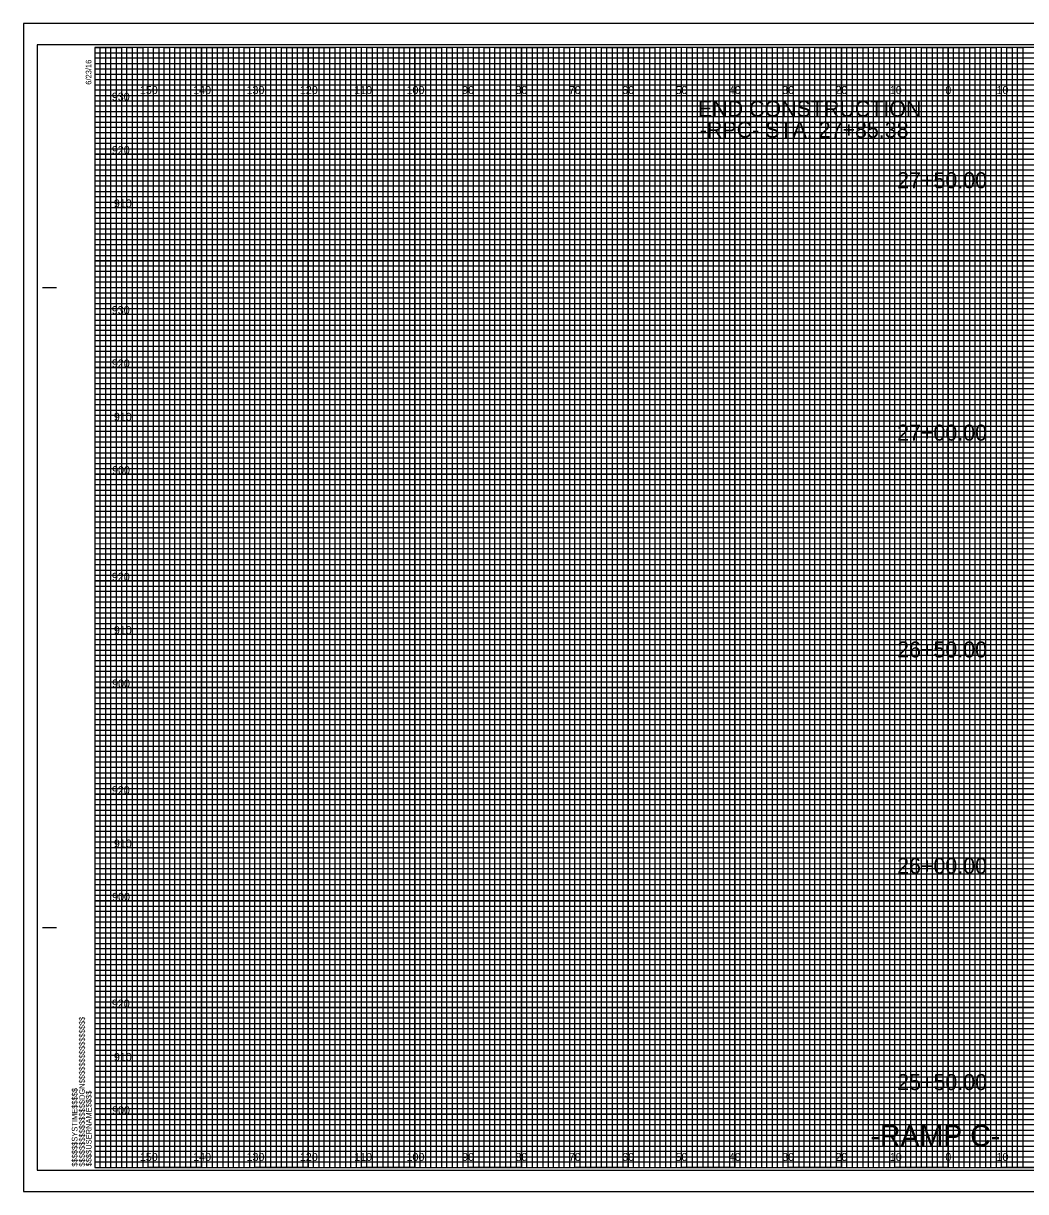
# Model space of a CAD drawing. Extents: x -13 to 323, y 876 to 1094.
# Drawn here: x -13.4 to 174.5, y 875.5 to 1094.5 of the extents above; entities that cross this region are included whole.
import ezdxf

# ---------------------------------------------------------------- set-up
doc = ezdxf.new("R2010")
doc.units = 0
for name, color, linetype in [('Prop XS Alignment Label', 7, 'Continuous'), ('Prop XS Elevation Labels', 7, 'Continuous'), ('Prop XS Offset Labels', 7, 'Continuous'), ('Prop XS SE Text', 7, 'Continuous'), ('Prop XS Station Labels', 7, 'Continuous'), ('Sheet Cross Section CELL', 7, 'Continuous'), ('Sheet Cross Section Grid Major CELL', 7, 'Continuous'), ('Sheet Cross Section Grid Middle CELL', 7, 'Continuous'), ('Sheet Cross Section Grid Minor 1 CELL', 7, 'Continuous'), ('Sheet Cross Section Grid Minor 2 CELL', 7, 'Continuous'), ('Sheet Cutting Line CELL', 7, 'Continuous'), ('Sheet DOT Grid CELL', 7, 'Continuous'), ('Sheet Plot Border Inside CELL', 7, 'Continuous'), ('Sheet Plot Border Outside CELL', 7, 'Continuous')]:
    doc.layers.add(name, color=color, linetype=linetype)

msp = doc.modelspace()

# ---------------------------------------------------------------- linework, layer by layer
at = {"layer": 'Sheet Cross Section CELL'}
for p, q in [((-9.8, 1045), (-7.3, 1045)), ((-9.7, 1045), (-7.2, 1045)), ((-9.8, 925), (-7.3, 925)), ((-9.7, 925), (-7.2, 925)), ((0, 880), (0, 880)), ((0, 880), (0, 880)), ((0, 880), (0, 880)), ((0, 880), (0, 880)), ((0, 880), (0, 880)), ((0, 880), (0, 880)), ((0, 880), (0, 880))]:
    msp.add_line(p, q, dxfattribs=at)
msp.add_lwpolyline([(320, 1090), (0, 1090), (0, 880), (320, 880)], close=True, dxfattribs=at)
at = {"layer": 'Sheet Cross Section Grid Major CELL'}
for p, q in [((10, 1090), (0, 1090)), ((10, 880), (10, 1090)), ((30, 1090), (20, 1090)), ((20, 1090), (20, 880)), ((30, 880), (30, 1090)), ((50, 1090), (40, 1090)), ((40, 1090), (40, 880)), ((50, 880), (50, 1090)), ((70, 1090), (60, 1090)), ((60, 1090), (60, 880)), ((70, 880), (70, 1090)), ((90, 1090), (80, 1090)), ((80, 1090), (80, 880)), ((90, 880), (90, 1090)), ((110, 1090), (100, 1090)), ((100, 1090), (100, 880)), ((110, 880), (110, 1090)), ((130, 1090), (120, 1090)), ((120, 1090), (120, 880)), ((130, 880), (130, 1090)), ((150, 1090), (140, 1090)), ((140, 1090), (140, 880)), ((150, 880), (150, 1090)), ((170, 1090), (160, 1090)), ((160, 1090), (160, 880)), ((170, 880), (170, 1090)), ((20, 880), (10, 880)), ((40, 880), (30, 880)), ((60, 880), (50, 880)), ((80, 880), (70, 880)), ((100, 880), (90, 880)), ((120, 880), (110, 880)), ((140, 880), (130, 880)), ((160, 880), (150, 880)), ((180, 880), (170, 880))]:
    msp.add_line(p, q, dxfattribs=at)
for points in [[(0, 1080), (320, 1080), (320, 1070), (0, 1070)], [(0, 1060), (320, 1060), (320, 1050), (0, 1050)], [(0, 1040), (320, 1040), (320, 1030), (0, 1030)], [(0, 1020), (320, 1020), (320, 1010), (0, 1010)], [(0, 1000), (320, 1000), (320, 990), (0, 990)], [(0, 980), (320, 980), (320, 970), (0, 970)], [(0, 960), (320, 960), (320, 950), (0, 950)], [(0, 940), (320, 940), (320, 930), (0, 930)], [(0, 920), (320, 920), (320, 910), (0, 910)], [(0, 900), (320, 900), (320, 890), (0, 890)]]:
    msp.add_lwpolyline(points, dxfattribs=at)
at = {"layer": 'Sheet Cross Section Grid Middle CELL'}
for points in [[(0, 1090), (5, 1090), (5, 880), (15, 880), (15, 1090), (25, 1090), (25, 880), (35, 880), (35, 1090), (45, 1090), (45, 880), (55, 880), (55, 1090), (65, 1090), (65, 880), (75, 880), (75, 1090), (85, 1090), (85, 880), (95, 880), (95, 1090), (105, 1090), (105, 880), (115, 880), (115, 1090), (125, 1090), (125, 880), (135, 880), (135, 1090), (145, 1090), (145, 880), (155, 880), (155, 1090), (165, 1090), (165, 880), (175, 880)], [(0, 1085), (275, 1085)], [(0, 1065), (320, 1065), (320, 1075), (0, 1075)], [(0, 1045), (320, 1045), (320, 1055), (0, 1055)], [(0, 1025), (320, 1025), (320, 1035), (0, 1035)], [(0, 1005), (320, 1005), (320, 1015), (0, 1015)], [(0, 985), (320, 985), (320, 995), (0, 995)], [(0, 965), (320, 965), (320, 975), (0, 975)], [(0, 945), (320, 945), (320, 955), (0, 955)], [(0, 925), (320, 925), (320, 935), (0, 935)], [(0, 905), (320, 905), (320, 915), (0, 915)], [(0, 885), (320, 885), (320, 895), (0, 895)]]:
    msp.add_lwpolyline(points, dxfattribs=at)
at = {"layer": 'Sheet Cross Section Grid Minor 1 CELL'}
for p, q in [((0, 1089), (260, 1089)), ((260, 1087.98), (0, 1087.98)), ((0, 1087.98), (0, 1087)), ((0, 1087), (260, 1087)), ((260, 1085.89), (0, 1085.89)), ((0, 1085.89), (0, 1084)), ((0, 1084), (320, 1084))]:
    msp.add_line(p, q, dxfattribs=at)
for points in [[(0, 1083), (270, 1083), (320, 1083), (320, 1082), (0, 1082)], [(0, 1081), (320, 1081), (320, 1079), (0, 1079)], [(0, 1078), (320, 1078), (320, 1077), (0, 1076.98)], [(0, 1076), (320, 1076), (320, 1074), (0, 1074)], [(0, 1073), (320, 1073), (320, 1072), (0, 1072)], [(0, 1071), (320, 1071), (320, 1069), (0, 1069)], [(0, 1068), (320, 1068), (320, 1067), (0, 1067)], [(0, 1066), (320, 1066), (320, 1064), (0, 1064)], [(0, 1063), (320, 1063), (320, 1062), (0, 1062)], [(0, 1061), (320, 1061), (320, 1059), (0, 1059)], [(0, 1058), (320, 1058), (320, 1057), (0, 1057)], [(0, 1056), (320, 1056), (320, 1053.95), (320, 1053), (320, 1052), (0, 1052)], [(0, 1054), (320, 1054), (320, 1053), (0, 1053)], [(0, 1051), (320, 1051), (320, 1049), (0, 1049.03)], [(0, 1049.03), (320, 1049), (320, 1048), (0, 1048)], [(0, 1047), (320, 1047), (320, 1046), (0, 1046)], [(0, 1044), (320, 1044), (320, 1043), (0, 1043)], [(0, 1042), (320, 1042), (320, 1041), (0, 1041)], [(-0.07, 1038.89), (320, 1038.89), (320, 1037.88), (-0.07, 1037.88)], [(0, 1037), (320, 1037), (320, 1036), (0, 1036)], [(0, 1034), (320, 1034), (320, 1033), (0, 1033)], [(0, 1032), (320, 1032), (320, 1031), (0, 1031)], [(0, 1029), (320, 1029), (320, 1028), (0, 1028)], [(0, 1027), (320, 1027), (320, 1026), (0, 1026)], [(0, 1024), (320, 1024), (320, 1023), (0, 1023)], [(0, 1022), (320, 1022), (320, 1021), (0, 1021)], [(0, 1019), (320, 1019), (319.99, 1017.98), (0, 1018)], [(0, 1017), (320, 1017), (320, 1016), (0, 1016)], [(0, 1014), (320, 1014), (320, 1013), (0, 1013)], [(0, 1012), (320, 1012), (320, 1011), (0, 1011)], [(0, 1009), (320, 1009), (320, 1008), (0, 1008)], [(0, 1007), (320, 1007), (320, 1006), (0, 1006)], [(0, 1004), (320, 1004), (320, 1003), (0, 1003)], [(0, 1002), (320, 1002), (320, 1001), (0, 1001)], [(0, 999), (320, 999), (320, 998), (0, 998)], [(0, 996.99), (320.07, 996.91), (320, 996), (0, 996)], [(0, 994), (320, 994), (320, 993), (0, 993)], [(0, 992), (320, 992), (320, 991), (0, 991)], [(0, 989), (320, 989), (320, 988), (0, 988)], [(0, 987), (320, 987), (320, 986), (0, 986)], [(0, 984), (320, 984), (320, 983), (0, 983)], [(0, 982), (320, 982), (320, 981), (0, 981)], [(0, 979), (320, 979), (320, 978), (0, 978)], [(0, 977), (320, 977), (320, 976), (0, 976)], [(0, 974), (320, 974), (320, 973), (0, 973)], [(0, 972), (320, 972), (320, 971), (0, 971)], [(0, 969), (320, 969), (320, 968), (0, 968)], [(0, 967), (320, 967), (320, 966), (0, 966)], [(0, 964), (320, 964), (320, 963), (0, 963)], [(0, 962), (320, 962), (320, 961), (0, 961)], [(0, 959), (320, 959), (319.99, 957.98), (0, 958)], [(0, 957), (320, 957), (320, 956), (0, 956)], [(0, 954), (320, 954), (320, 953), (0, 953)], [(0, 952), (320, 952), (320, 951), (0, 951)], [(0, 949), (320, 949), (320, 948), (0, 948)], [(0, 947), (320, 947), (320, 946), (0, 946)], [(0, 944), (320, 944), (320, 943), (0, 943)], [(0, 942), (320, 942), (320, 941), (0, 941)], [(0, 939), (320, 939), (320, 938), (0, 938)], [(0, 936.99), (320.07, 936.91), (320, 936), (0, 936)], [(0, 934), (320, 934), (320, 933), (0, 933)], [(0, 932), (320, 932), (320, 931), (0, 931)], [(0, 929), (320, 929), (320, 928), (0, 928)], [(0, 927), (320, 927), (320, 926), (0, 926)], [(0, 924), (320, 924), (320, 923), (0, 923)], [(0, 922), (320, 922), (320, 921), (0, 921)], [(0, 919), (320, 919), (320, 918), (0, 918)], [(0, 917), (320, 917), (320, 916), (0, 916)], [(0, 914), (320, 914), (320, 913), (0, 913)], [(0, 912), (320, 912), (320, 911), (0, 911)], [(0, 909), (320, 909), (320, 908), (0, 908)], [(0, 907), (320, 907), (320, 906), (0, 906)], [(0, 904), (320, 904), (320, 903), (0, 903)], [(0, 902), (320, 902), (320, 901), (0, 901)], [(0, 899), (320, 899), (320, 898), (0, 898)], [(0, 897), (320, 897), (320, 896), (0, 896)], [(0, 894), (320, 894), (320, 893), (0, 893)], [(0, 892), (320, 892), (320, 891), (0, 891)], [(0, 889), (320, 889), (320, 888), (0, 888)], [(0, 887), (320, 887), (320, 886), (0, 886)], [(0, 884), (320, 884), (320, 883), (0, 883)], [(0, 882), (320, 882), (320, 881), (0, 881)]]:
    msp.add_lwpolyline(points, dxfattribs=at)
at = {"layer": 'Sheet Cross Section Grid Minor 2 CELL'}
for points in [[(0, 880), (1, 880), (1, 1090), (2, 1090), (2, 880)], [(2, 880), (3, 880), (3, 1090), (4, 1090), (4, 880)], [(5, 880), (6, 880), (6, 1090), (7, 1090), (7, 880)], [(7, 880), (8, 880), (8, 1090), (9, 1090), (9, 880)], [(10, 880), (11, 880), (11, 1090), (12, 1090), (12, 880)], [(12, 880), (13, 880), (13, 1090), (14, 1090), (14, 880)], [(15, 880), (16, 880), (16, 1090), (17, 1090), (17, 880)], [(17, 880), (18, 880), (18, 1090), (19, 1090), (19, 880)], [(20, 880), (21, 880), (21, 1090), (22, 1090), (22, 880)], [(22, 880), (23, 880), (23, 1090), (24, 1090), (24, 880)], [(25, 880), (26, 880), (26, 1090), (27, 1090), (27, 880)], [(27, 880), (28, 880), (28, 1090), (29, 1090), (29, 880)], [(30, 880), (31, 880), (31, 1090), (32, 1090), (32, 880)], [(32, 880), (33, 880), (33, 1090), (34, 1090), (34, 880)], [(35, 880), (36, 880), (36, 1090), (37, 1090), (37, 880)], [(37, 880), (38, 880), (38, 1090), (39, 1090), (39, 880)], [(40, 880), (41, 880), (41, 1090), (42, 1090), (42, 880)], [(42, 880), (43, 880), (43, 1090), (44, 1090), (44, 880)], [(45, 880), (46, 880), (46, 1090), (47, 1090), (47, 880)], [(47, 880), (48, 880), (48, 1090), (49, 1090), (49, 880)], [(50, 880), (51, 880), (51, 1090), (52, 1090), (52, 880)], [(52, 880), (53, 880), (53, 1090), (54, 1090), (54, 880)], [(55, 880), (56, 880), (56, 1090), (57, 1090), (57, 880)], [(57, 880), (58, 880), (58, 1090), (59, 1090), (59, 880)], [(60, 880), (61, 880), (61, 1090), (62, 1090), (62, 880)], [(62, 880), (63, 880), (63, 1090), (64, 1090), (64, 880)], [(65, 880), (66, 880), (66, 1090), (67, 1090), (67, 880)], [(67, 880), (68, 880), (68, 1090), (69, 1090), (69, 880)], [(70, 880), (71, 880), (71, 1090), (72, 1090), (72, 880)], [(72, 880), (73, 880), (73, 1090), (74, 1090), (74, 880)], [(75, 880), (76, 880), (76, 1090), (77, 1090), (77, 880)], [(77, 880), (78, 880), (78, 1090), (79, 1090), (79, 880)], [(80, 880), (81, 880), (81, 1090), (82, 1090), (82, 880)], [(82, 880), (83, 880), (83, 1090), (84, 1090), (84, 880)], [(85, 880), (86, 880), (86, 1090), (87, 1090), (87, 880)], [(87, 880), (88, 880), (88, 1090), (89, 1090), (89, 880)], [(90, 880), (91, 880), (91, 1090), (92, 1090), (92, 880)], [(92, 880), (93, 880), (93, 1090), (94, 1090), (94, 880)], [(95, 880), (96, 880), (96, 1090), (97, 1090), (97, 880)], [(97, 880), (98, 880), (98, 1090), (99, 1090), (99, 880)], [(100, 880), (101, 880), (101, 1090), (102, 1090), (102, 880)], [(102, 880), (103, 880), (103, 1090), (104, 1090), (104, 880)], [(105, 880), (106, 880), (106, 1090), (107, 1090), (107, 880)], [(107, 880), (108, 880), (108, 1090), (109, 1090), (109, 880)], [(110, 880), (111, 880), (111, 1090), (112, 1090), (112, 880)], [(112, 880), (113, 880), (113, 1090), (114, 1090), (114, 880)], [(115, 880), (116, 880), (116, 1090), (117, 1090), (117, 880)], [(117, 880), (118, 880), (118, 1090), (119, 1090), (119, 880)], [(120, 880), (121, 880), (121, 1090), (122, 1090), (122, 880)], [(122, 880), (123, 880), (123, 1090), (124, 1090), (124, 880)], [(125, 880), (126, 880), (126, 1090), (127, 1090), (127, 880)], [(127, 880), (128, 880), (128, 1090), (129, 1090), (129, 880)], [(130, 880), (131, 880), (131, 1090), (132, 1090), (132, 880)], [(132, 880), (133, 880), (133, 1090), (134, 1090), (134, 880)], [(135, 880), (136, 880), (136, 1090), (137, 1090), (137, 880)], [(137, 880), (138, 880), (138, 1090), (139, 1090), (139, 880)], [(140, 880), (141, 880), (141, 1090), (142, 1090), (142, 880)], [(142, 880), (143, 880), (143, 1090), (144, 1090), (144, 880)], [(145, 880), (146, 880), (146, 1090), (147, 1090), (147, 880)], [(147, 880), (148, 880), (148, 1090), (149, 1090), (149, 880)], [(150, 880), (151, 880), (151, 1090), (152, 1090), (152, 880)], [(152, 880), (153, 880), (153, 1090), (154, 1090), (154, 880)], [(155, 880), (156, 880), (156, 1090), (157, 1090), (157, 880)], [(157, 880), (158, 880), (158, 1090), (159, 1090), (159, 880)], [(160, 880), (161, 880), (161, 1090), (162, 1090), (162, 880)], [(162, 880), (163, 880), (163, 1090), (164, 1090), (164, 880)], [(165, 880), (166, 880), (166, 1090), (167, 1090), (167, 880)], [(167, 880), (168, 880), (168, 1090), (169, 1090), (169, 880)], [(170, 880), (171, 880), (171, 1090), (172, 1090), (172, 880)], [(172, 880), (173, 880), (173, 1090), (174, 1090), (174, 880)]]:
    msp.add_lwpolyline(points, dxfattribs=at)
at = {"layer": 'Sheet Cutting Line CELL'}
for p, q in [((323.3, 1094.5), (-13.4, 1094.5)), ((-13.4, 1094.5), (-13.4, 875.5)), ((-13.4, 875.5), (323.3, 875.5))]:
    msp.add_line(p, q, dxfattribs=at)
at = {"layer": 'Sheet DOT Grid CELL'}
for p, q in [((10, 880), (10, 1090)), ((20, 880), (20, 1090)), ((30, 880), (30, 1090)), ((40, 880), (40, 1090)), ((50, 880), (50, 1090)), ((60, 880), (60, 1090)), ((70, 880), (70, 1090)), ((80, 880), (80, 1090)), ((90, 880), (90, 1090)), ((100, 880), (100, 1090)), ((110, 880), (110, 1090)), ((120, 880), (120, 1090)), ((130, 880), (130, 1090)), ((140, 880), (140, 1090)), ((150, 880), (150, 1090)), ((160, 880), (160, 1090)), ((170, 880), (170, 1090)), ((0, 1080), (320, 1080)), ((0, 1070), (320, 1070)), ((0, 1060), (320, 1060)), ((0, 1050), (320, 1050)), ((0, 1040), (320, 1040)), ((0, 1030), (320, 1030)), ((0, 1020), (320, 1020)), ((0, 1010), (320, 1010)), ((0, 1000), (320, 1000)), ((0, 990), (320, 990)), ((0, 980), (320, 980)), ((0, 970), (320, 970)), ((0, 960), (320, 960)), ((0, 950), (320, 950)), ((0, 940), (320, 940)), ((0, 930), (320, 930)), ((0, 920), (320, 920)), ((0, 910), (320, 910)), ((0, 900), (320, 900)), ((0, 890), (320, 890))]:
    msp.add_line(p, q, dxfattribs=at)
at = {"layer": 'Sheet Plot Border Inside CELL'}
msp.add_lwpolyline([(-10.8, 879.5), (322.4, 879.5), (322.4, 1090.5), (-10.8, 1090.5)], close=True, dxfattribs=at)
at = {"layer": 'Sheet Plot Border Outside CELL'}
msp.add_lwpolyline([(-13.4, 875.5), (323.3, 875.5), (323.3, 1094.5), (-13.4, 1094.5)], close=True, dxfattribs=at)

# ---------------------------------------------------------------- texts
at = {"layer": 'Prop XS Alignment Label'}
msp.add_text('-RAMP C-', height=4, dxfattribs=at).set_placement((145.39, 884))
at = {"layer": 'Prop XS Elevation Labels'}
for s, p in [('930', (3.18, 1080)), ('920', (3.19, 1070)), ('910', (3.57, 1060)), ('930', (3.18, 1040)), ('920', (3.19, 1030)), ('910', (3.57, 1020)), ('900', (3.24, 1010)), ('920', (3.19, 990)), ('910', (3.57, 980)), ('900', (3.24, 970)), ('920', (3.19, 950)), ('910', (3.57, 940)), ('900', (3.24, 930)), ('920', (3.19, 910)), ('910', (3.57, 900)), ('900', (3.24, 890))]:
    msp.add_text(s, height=1.5, dxfattribs=at).set_placement(p)
at = {"layer": 'Prop XS Offset Labels'}
for s, p in [('150', (8.44, 1081.25)), ('140', (18.44, 1081.25)), ('130', (28.44, 1081.25)), ('120', (38.44, 1081.25)), ('110', (48.62, 1081.25)), ('100', (58.44, 1081.25)), ('90', (68.86, 1081.25)), ('80', (78.86, 1081.25)), ('70', (88.86, 1081.25)), ('60', (98.86, 1081.25)), ('50', (108.86, 1081.25)), ('40', (118.86, 1081.25)), ('30', (128.86, 1081.25)), ('20', (138.86, 1081.25)), ('10', (149.04, 1081.25)), ('0', (159.45, 1081.25)), ('0', (159.45, 1081.25)), ('10', (169.04, 1081.25)), ('150', (8.44, 881.25)), ('140', (18.44, 881.25)), ('130', (28.44, 881.25)), ('120', (38.44, 881.25)), ('110', (48.62, 881.25)), ('100', (58.44, 881.25)), ('90', (68.86, 881.25)), ('80', (78.86, 881.25)), ('70', (88.86, 881.25)), ('60', (98.86, 881.25)), ('50', (108.86, 881.25)), ('40', (118.86, 881.25)), ('30', (128.86, 881.25)), ('20', (138.86, 881.25)), ('10', (149.04, 881.25)), ('0', (159.45, 881.25)), ('0', (159.45, 881.25)), ('10', (169.04, 881.25))]:
    msp.add_text(s, height=1.5, dxfattribs=at).set_placement(p)
at = {"layer": 'Prop XS SE Text'}
for s, p in [('END CONSTRUCTION', (113.06, 1077)), ('-RPC- STA. 27+85.38', (113.42, 1073.07))]:
    msp.add_text(s, height=3, rotation=359.9987, dxfattribs=at).set_placement(p)
at = {"layer": 'Prop XS Station Labels'}
for s, p in [('27+50.00', (150.41, 1063.6)), ('27+00.00', (150.41, 1016.28)), ('26+50.00', (150.41, 975.63)), ('26+00.00', (150.41, 935.09)), ('25+50.00', (150.41, 894.54))]:
    msp.add_text(s, height=3, dxfattribs=at).set_placement(p)
at = {"layer": 'Sheet Cross Section CELL'}
for s, p in [('6/23/16', (-0.65, 1083)), ('$$$$$$$$$$$$$$$$DGN$$$$$$$$$$$$$$$$', (-1.88, 880.18)), ('$$$$$$SYSTIME$$$$$', (-3.26, 880.18)), ('$$$$USERNAME$$$$', (-0.62, 880.23))]:
    msp.add_text(s, height=1.05, rotation=90, dxfattribs=at).set_placement(p)

doc.saveas('drawing.dxf')
